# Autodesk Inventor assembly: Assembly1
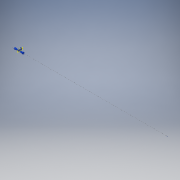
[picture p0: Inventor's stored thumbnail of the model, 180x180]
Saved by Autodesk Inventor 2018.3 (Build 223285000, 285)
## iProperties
Created: 2013-11
Part Number: Assembly1
Document SubType Name: Assembly
Designer: Warren
Author: Warren
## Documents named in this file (7)
- C:\Nui Galway 2020-2021\Inventor Training Material 2020-2021\Biomedical Engineering Year 3\Tutor\Catheter\Assembly1.iam
- C:\Nui Galway 2020-2021\Inventor Training Material 2020-2021\Biomedical Engineering Year 3\Tutor\Catheter\Hub.ipt
- C:\Nui Galway 2020-2021\Inventor Training Material 2020-2021\Biomedical Engineering Year 3\Tutor\Catheter\Inflation Catheter.ipt
- C:\Nui Galway 2020-2021\Inventor Training Material 2020-2021\Biomedical Engineering Year 3\Tutor\Catheter\stentrod.ipt
- C:\Nui Galway 2020-2021\Inventor Training Material 2020-2021\Biomedical Engineering Year 3\Tutor\Catheter\Balloon.ipt
- C:\Nui Galway 2020-2021\Inventor Training Material 2020-2021\Biomedical Engineering Year 3\Tutor\Catheter\Inflation Catheter Outer.ipt
- C:\Nui Galway 2020-2021\Inventor Training Material 2020-2021\Biomedical Engineering Year 3\Tutor\Catheter\guidewire.ipt
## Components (6 placed, 6 different names)
1. Hub:1 — Insert:2
2. Inflation Catheter:1 — Insert:4
3. stentrod:1 — Mate:4
4. Balloon:1 — Insert:3
5. Inflation Catheter Outer:1 — Insert:2, Insert:3, Mate:4
6. guidewire:1 — Insert:4
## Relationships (4: Insert 3, Mate 1)
- Insert:2: Hub:1 ↔ Inflation Catheter Outer:1
- Insert:3: Balloon:1 ↔ Inflation Catheter Outer:1
- Mate:4: stentrod:1 ↔ Inflation Catheter Outer:1
- Insert:4: Inflation Catheter:1 ↔ guidewire:1
